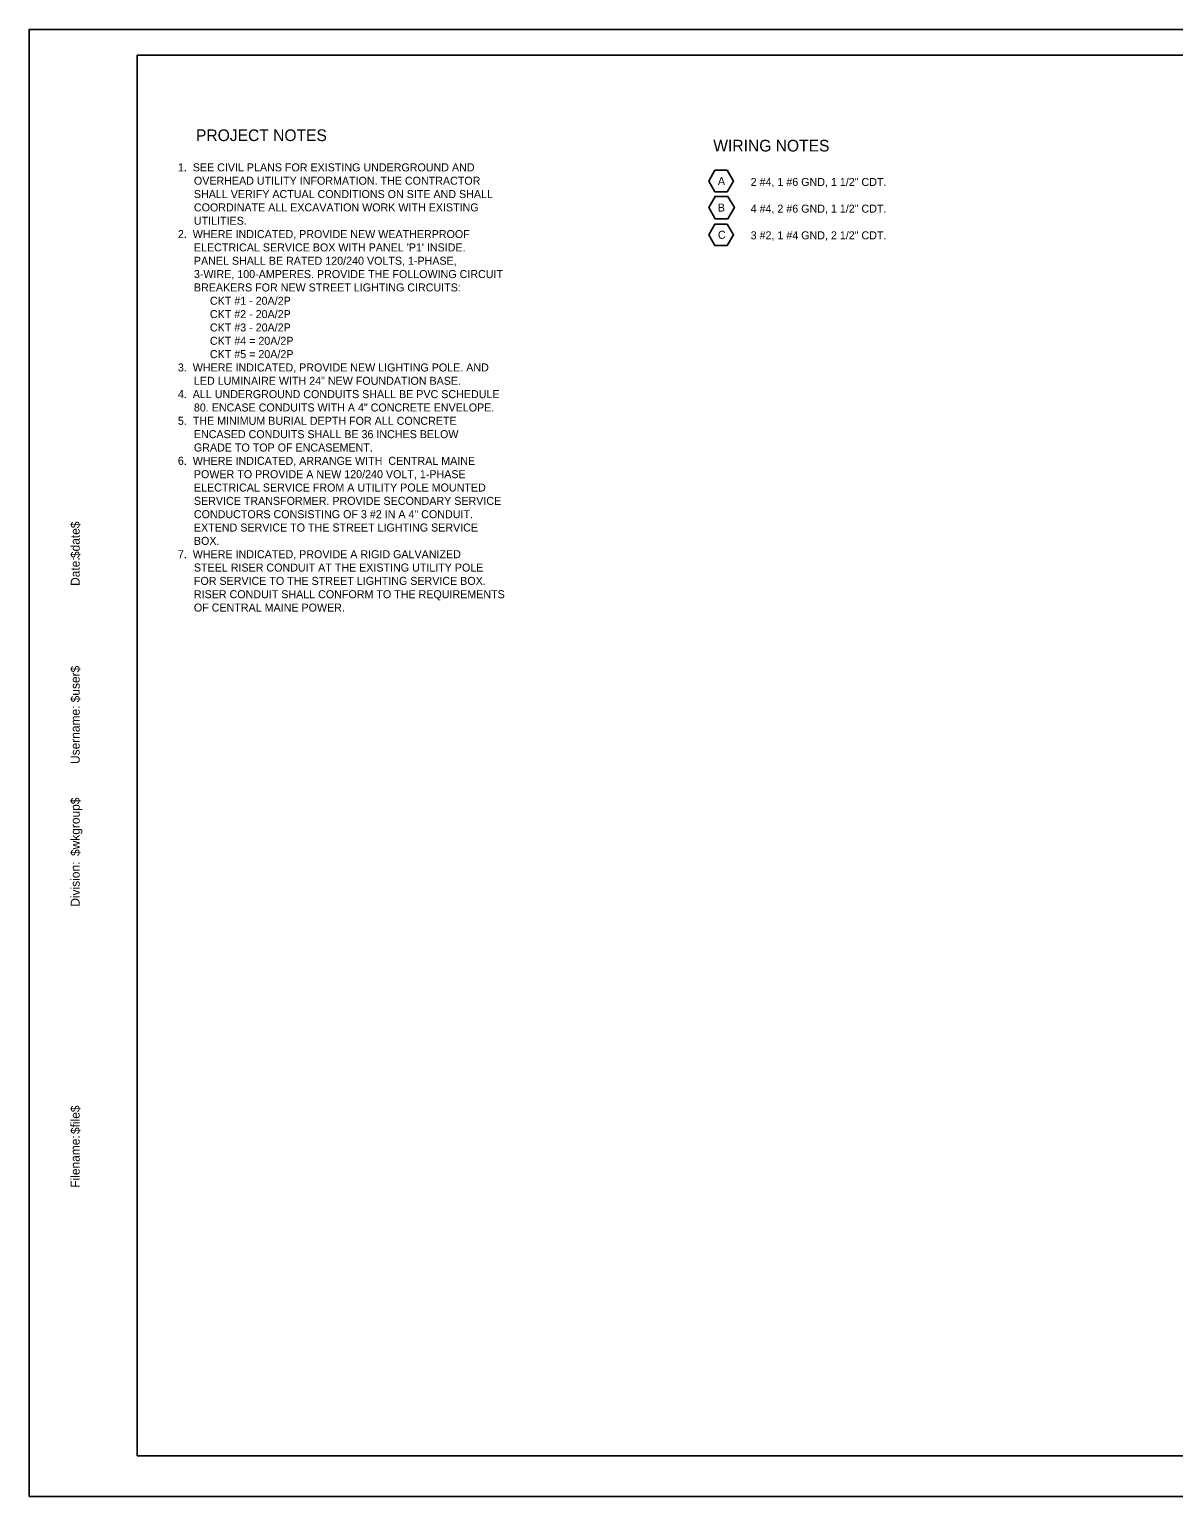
# Model space of a CAD drawing. Extents: x 9916 to 916479, y 6678 to 329942.
# Drawn here: x 915621 to 916050, y 329392 to 329942 of the extents above; entities that cross this region are included whole.
import ezdxf

# ---------------------------------------------------------------- set-up
doc = ezdxf.new("R2010")
doc.units = 0
for name, color, linetype in [('ANNOTATION', 7, 'Continuous'), ('Border', 7, 'Continuous'), ('PLOT BOUNDARY', 7, 'Continuous')]:
    doc.layers.add(name, color=color, linetype=linetype)

msp = doc.modelspace()

# ---------------------------------------------------------------- linework, layer by layer
at = {"layer": 'ANNOTATION'}
for points in [[(915882.9, 329888.88), (915878.24, 329888.88), (915875.91, 329884.84), (915878.24, 329880.8), (915882.9, 329880.8), (915885.24, 329884.84)], [(915883.14, 329879.06), (915878.32, 329879.06), (915875.91, 329874.88), (915878.32, 329870.7), (915883.14, 329870.7), (915885.55, 329874.88)], [(915882.9, 329868.72), (915878.24, 329868.72), (915875.91, 329864.69), (915878.24, 329860.65), (915882.9, 329860.65), (915885.24, 329864.69)]]:
    msp.add_lwpolyline(points, close=True, dxfattribs=at)
at = {"layer": 'Border'}
for p, q in [((916461.64, 329932), (915661.64, 329932)), ((915661.64, 329932), (915661.64, 329407)), ((915661.64, 329407), (916461.64, 329407))]:
    msp.add_line(p, q, dxfattribs=at)
at = {"layer": 'PLOT BOUNDARY'}
msp.add_lwpolyline([(915621.17, 329391.7), (916471.17, 329391.7), (916471.17, 329941.7), (915621.17, 329941.7)], close=True, dxfattribs=at)

# ---------------------------------------------------------------- texts
at = {"layer": 'ANNOTATION'}
for s, height, p in [('PROJECT NOTES', 4.375, (915683.67, 329899.82)), ('WIRING NOTES', 4.375, (915877.64, 329895.92)), ('1.  SEE CIVIL PLANS FOR EXISTING UNDERGROUND AND ', 3, (915676.88, 329888.46)), ('OVERHEAD UTILITY INFORMATION. THE CONTRACTOR ', 3, (915682.88, 329883.46)), ('A', 3, (915879.37, 329883.34)), ('2 #4, 1 #6 GND, 1 1/2" CDT.', 3, (915891.65, 329882.99)), ('SHALL VERIFY ACTUAL CONDITIONS ON SITE AND SHALL ', 3, (915682.88, 329878.46)), ('COORDINATE ALL EXCAVATION WORK WITH EXISTING ', 3, (915682.88, 329873.46)), ('B', 3, (915879.32, 329873.38)), ('4 #4, 2 #6 GND, 1 1/2" CDT.', 3, (915891.65, 329872.99)), ('UTILITIES.', 3, (915682.88, 329868.46)), ('2.  WHERE INDICATED, PROVIDE NEW WEATHERPROOF ', 3, (915676.88, 329863.46)), ('C', 3, (915879.37, 329863.19)), ('3 #2, 1 #4 GND, 2 1/2" CDT.', 3, (915891.65, 329862.99)), ("ELECTRICAL SERVICE BOX WITH PANEL 'P1' INSIDE. ", 3, (915682.88, 329858.46)), ('PANEL SHALL BE RATED 120/240 VOLTS, 1-PHASE, ', 3, (915682.88, 329853.46)), ('3-WIRE, 100-AMPERES. PROVIDE THE FOLLOWING CIRCUIT ', 3, (915682.88, 329848.46)), ('BREAKERS FOR NEW STREET LIGHTING CIRCUITS:', 3, (915682.88, 329843.46)), ('CKT #1 - 20A/2P', 3, (915688.88, 329838.46)), ('CKT #2 - 20A/2P', 3, (915688.88, 329833.46)), ('CKT #3 - 20A/2P', 3, (915688.88, 329828.46)), ('CKT #4 = 20A/2P', 3, (915688.88, 329823.46)), ('CKT #5 = 20A/2P', 3, (915688.88, 329818.46)), ('3.  WHERE INDICATED, PROVIDE NEW LIGHTING POLE. AND ', 3, (915676.88, 329813.46)), ('LED LUMINAIRE WITH 24" NEW FOUNDATION BASE.', 3, (915682.88, 329808.46)), ('4.  ALL UNDERGROUND CONDUITS SHALL BE PVC SCHEDULE ', 3, (915676.88, 329803.46)), ('80. ENCASE CONDUITS WITH A 4" CONCRETE ENVELOPE.', 3, (915682.88, 329798.46)), ('5.  THE MINIMUM BURIAL DEPTH FOR ALL CONCRETE ', 3, (915676.88, 329793.46)), ('ENCASED CONDUITS SHALL BE 36 INCHES BELOW ', 3, (915682.88, 329788.46)), ('GRADE TO TOP OF ENCASEMENT.', 3, (915682.88, 329783.46)), ('6.  WHERE INDICATED, ARRANGE WITH  CENTRAL MAINE ', 3, (915676.88, 329778.46)), ('POWER TO PROVIDE A NEW 120/240 VOLT, 1-PHASE ', 3, (915682.88, 329773.46)), ('ELECTRICAL SERVICE FROM A UTILITY POLE MOUNTED ', 3, (915682.88, 329768.46)), ('SERVICE TRANSFORMER. PROVIDE SECONDARY SERVICE ', 3, (915682.88, 329763.46)), ('CONDUCTORS CONSISTING OF 3 #2 IN A 4" CONDUIT. ', 3, (915682.88, 329758.46)), ('EXTEND SERVICE TO THE STREET LIGHTING SERVICE ', 3, (915682.88, 329753.46)), ('7.  WHERE INDICATED, PROVIDE A RIGID GALVANIZED ', 3, (915676.88, 329743.46)), ('BOX.', 3, (915682.88, 329748.46)), ('STEEL RISER CONDUIT AT THE EXISTING UTILITY POLE ', 3, (915682.88, 329738.46)), ('FOR SERVICE TO THE STREET LIGHTING SERVICE BOX. ', 3, (915682.88, 329733.46)), ('RISER CONDUIT SHALL CONFORM TO THE REQUIREMENTS ', 3, (915682.88, 329728.46)), ('OF CENTRAL MAINE POWER.', 3, (915682.88, 329723.46))]:
    msp.add_text(s, height=height, dxfattribs=at).set_placement(p)
at = {"layer": 'Border'}
for s, p in [('$date$', (915640.06, 329743.52)), ('Date:', (915640.06, 329733.08)), ('$user$', (915640.06, 329689.45)), ('Username:', (915640.06, 329666.33)), ('$wkgroup$', (915640.06, 329631.84)), ('Division:', (915640.06, 329612.83)), ('$file$', (915640.06, 329527.62)), ('Filename:', (915640.06, 329507.49))]:
    msp.add_text(s, height=3.348, rotation=90, dxfattribs=at).set_placement(p)

doc.saveas('drawing.dxf')
